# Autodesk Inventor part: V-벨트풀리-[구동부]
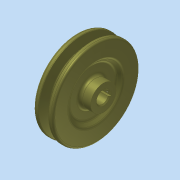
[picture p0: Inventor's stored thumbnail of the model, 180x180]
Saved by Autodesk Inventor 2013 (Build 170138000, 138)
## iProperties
Company: 한국ATC센터
Created: 2009-02
Part Number: V-벨트풀리-[구동부]
Document SubType Name: Modeling
Designer: KYOUNG IL JANG
Density: 7.25 g/cm^3
Mass: 594.644 g
Surface Area: 210.328 cm^2
Volume: 82.0198 cm^3
Material: 주철
Vendor: CBT Solutions
Author: KYOUNG IL JANG
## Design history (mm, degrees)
sketch "스케치1"
  geometry: L1 (-13, 0)-(13, 0); L2 (-13, 0)-(-13, 12.5); L3 (-13, 12.5)-(-9, 12.5); L4 (-9, 12.5)-(-9, 23); L5 (-9, 23)-(-13, 27); L6 (-13, 27)-(-13, 42.7); L7 (-13, 42.7)-(-8.325, 42.7); L8 (-8.325, 42.7)-(-5.574, 33.7); L9 (-5.574, 33.7)-(-1.426, 33.7); L10 (-1.426, 33.7)-(1.325, 42.7); L11 (1.325, 42.7)-(6, 42.7); L12 (6, 42.7)-(6, 27); L13 (6, 27)-(2, 23); L14 (2, 23)-(2, 12.5); L15 (2, 12.5)-(13, 12.5); L16 (13, 12.5)-(13, 0); L17 (-7.5, 40)-(0.5, 40); 2 further points
  constraints: 34 end point, 6 parallel, 5 collinear, 5 equal length, 4 perpendicular, 2 point on line, 1 coincident, 1 horizontal, 1 midpoint
  dimensions: "d0" = 26 distance of L1.start L1.end; "d1" = 2.7 distance between parallel lines of L7 L17; "d2" = 6.3 distance between parallel lines of L9 L17; "d3" = 8 distance of L17.start L17.end; "d4" = 34 deg angle of L10 L8; "d5" = 19 distance between parallel lines of L12 L6; "d7" = 25 diameter of L15 L1; "d8" = 46 diameter of L13.end L1; "d9" = 54 diameter of L12.end L1; "d10" = 4 distance between parallel lines of L2 L4; "d11" = 80 diameter of L17 L1
revolve "회전1" sketch "스케치1" stored, may be unused: angle "d12" = 90 deg
sketch "스케치2"
  geometry: L1 (-2, 5.657)-(-2, 7.8); L2 (-2, 7.8)-(2, 7.8); L3 (2, 7.8)-(2, 5.657); A1 r 6 centre (0, 0) between (-2, 5.657) and (2, 5.657); 1 further point
  constraints: 6 end point, 2 parallel, 2 point on circle, 1 centre point, 1 coincident, 1 perpendicular, 1 vertical
  dimensions: "d13" = 12 diameter of A1; "d14" = 13.8 dimension on A1 L2; "d15" = 4 distance of L1.end L2.end
extrude "돌출1" cut sketch "스케치2" stored distance "d16" = 10; taper "d17" = 0 deg
node "작업 평면1"
sketch "스케치3"
  geometry: L1 (-5.5, 12.5)-(-5.5, -12.5) reference; 3 further points
  constraints: 1 horizontal alignment, 1 midpoint
  dimensions: "d18" = 4 distance from line of point (-1.5, 0) L1
hole "구멍1" sketch "스케치3" at (-1.5, 0) diameter "d19" = 2.459; stored, may be unused: countersink angle "d23" = 90 deg, drill point angle "d25" = 118 deg; dims "d20" = 6, "d21" = 4, "d22" = 2, "d24" = 8
fillet "모깎기1" dims "d26" = 2, "d27" = 0.5, "d28" = 1, "d29" = 3
chamfer "모따기1" distance "d30" = 1; stored, may be unused: second distance "d31" = 2, angle "d32" = 45 deg
node "솔리드1"
